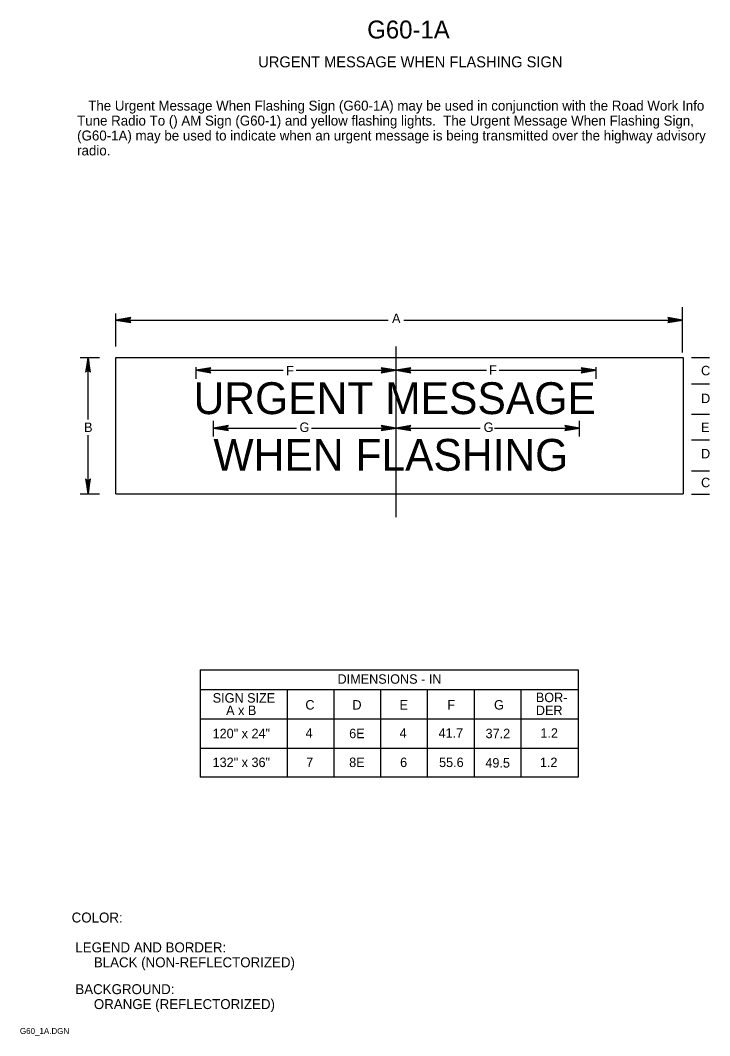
# Model space of a CAD drawing. Extents: x 0.012 to 0.185, y 0.004 to 0.259.
import ezdxf

# ---------------------------------------------------------------- set-up
doc = ezdxf.new("R2010")
doc.units = 0
doc.layers.add('1', color=7, linetype='Continuous')
doc.layers.add('3', color=7, linetype='Continuous')

# ---------------------------------------------------------------- blocks, each defined once
blk = doc.blocks.new('RARROW')
at = {"layer": '3'}
for p, q in [((-2.156, 0.285), (-2.2665, 0.384625)), ((-2.2665, 0.384625), (0, 0)), ((0, 0), (-2.2665, -0.379125)), ((-2.156, 0.285), (-2.075625, 0.12075)), ((0, 0), (-2.156, 0.285)), ((-2.14975, -0.2705), (0, 0)), ((-2.075625, 0.12075), (0, 0)), ((0, 0), (-2.074, -0.108)), ((-2.2665, -0.379125), (-2.14975, -0.2705)), ((-2.074, -0.108), (-2.14975, -0.2705))]:
    blk.add_line(p, q, dxfattribs=at)

msp = doc.modelspace()

# ---------------------------------------------------------------- linework, layer by layer
at = {"layer": '1'}
for p, q in [((0.17863, 0.17563), (0.17863, 0.187)), ((0.03625, 0.17713), (0.03625, 0.18538)), ((0.03625, 0.18375), (0.10462, 0.18375)), ((0.10862, 0.18375), (0.17863, 0.18375)), ((0.10662, 0.13425), (0.10662, 0.17713)), ((0.02725, 0.17438), (0.03213, 0.17438)), ((0.02925, 0.15875), (0.02925, 0.17438)), ((0.03625, 0.17438), (0.17875, 0.17438)), ((0.03625, 0.14012), (0.03625, 0.17438)), ((0.17875, 0.17438), (0.17875, 0.14012)), ((0.18088, 0.17438), (0.18538, 0.17438)), ((0.05638, 0.169), (0.05638, 0.17188)), ((0.05638, 0.17112), (0.07829, 0.17112)), ((0.0815, 0.17112), (0.10662, 0.17112)), ((0.10662, 0.16837), (0.10662, 0.17313)), ((0.10662, 0.17112), (0.12939, 0.17112)), ((0.1325, 0.17112), (0.15688, 0.17112)), ((0.15688, 0.169), (0.15688, 0.17188)), ((0.18088, 0.16775), (0.18538, 0.16775)), ((0.06074, 0.15453), (0.06074, 0.1584)), ((0.10662, 0.15453), (0.10662, 0.1584)), ((0.15275, 0.15453), (0.15275, 0.1584)), ((0.18088, 0.16012), (0.18538, 0.16012)), ((0.06086, 0.15663), (0.08163, 0.15663)), ((0.08535, 0.15663), (0.10662, 0.15663)), ((0.10662, 0.15663), (0.12775, 0.15663)), ((0.13139, 0.15663), (0.15275, 0.15663)), ((0.02925, 0.14012), (0.02925, 0.15481)), ((0.18088, 0.15363), (0.18538, 0.15363)), ((0.18088, 0.14588), (0.18538, 0.14588)), ((0.02725, 0.14012), (0.03213, 0.14012)), ((0.03625, 0.14012), (0.17875, 0.14012)), ((0.18088, 0.14), (0.18538, 0.14))]:
    msp.add_line(p, q, dxfattribs=at)
at = {"layer": '3'}
for p, q in [((0.05738, 0.09588), (0.15238, 0.09588)), ((0.05738, 0.09588), (0.05738, 0.06888)), ((0.15238, 0.09588), (0.15238, 0.06888)), ((0.15238, 0.09087), (0.05738, 0.09087)), ((0.07923, 0.0908), (0.07923, 0.06888)), ((0.09098, 0.0908), (0.09098, 0.06888)), ((0.10273, 0.0908), (0.10273, 0.06888)), ((0.10273, 0.0908), (0.10273, 0.07705)), ((0.11448, 0.0908), (0.11448, 0.06888)), ((0.12623, 0.0908), (0.12623, 0.06888)), ((0.13798, 0.0908), (0.13798, 0.06888)), ((0.15238, 0.0835), (0.05738, 0.0835)), ((0.15238, 0.07612), (0.05738, 0.07612)), ((0.15238, 0.06888), (0.05738, 0.06888))]:
    msp.add_line(p, q, dxfattribs=at)

# ---------------------------------------------------------------- block references
at = {"layer": '3', "xscale": 0.0016545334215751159, "yscale": -0.0016366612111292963}
for p, rotation in [((0.03625, 0.18375), 180), ((0.02925, 0.17438), 89.99999999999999), ((0.05638, 0.17112), 180), ((0.10662, 0.17112), 180), ((0.06075, 0.15663), 180), ((0.10662, 0.15663), 180), ((0.02925, 0.14012), -90.00000000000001)]:
    msp.add_blockref('RARROW', p, dxfattribs=dict(at, rotation=rotation))
for p in [(0.17863, 0.18375), (0.10662, 0.17112), (0.15688, 0.17112), (0.10662, 0.15663), (0.15275, 0.15663)]:
    msp.add_blockref('RARROW', p, dxfattribs=at)

# ---------------------------------------------------------------- texts
at = {"layer": '1'}
for s, height, p in [('G60-1A', 0.0045, (0.09938, 0.2545)), ('URGENT MESSAGE WHEN FLASHING SIGN', 0.0027503, (0.072, 0.24725)), ('   The Urgent Message When Flashing Sign (G60-1A) may be used in conjunction with the Road Work Info', 0.0024998, (0.0265, 0.23638)), ('Tune Radio To () AM Sign (G60-1) and yellow flashing lights.  The Urgent Message When Flashing Sign,', 0.0024998, (0.0265, 0.23262)), ('(G60-1A) may be used to indicate when an urgent message is being transmitted over the highway advisory', 0.00249975, (0.0265, 0.22887)), ('radio.', 0.0025, (0.0265, 0.22512)), ('A', 0.00238, (0.10562, 0.183)), ('F', 0.00238, (0.079, 0.16987)), ('F', 0.00238, (0.13, 0.17)), ('C', 0.00238, (0.18325, 0.16987)), ('URGENT MESSAGE', 0.0080003, (0.05575, 0.16012)), ('D', 0.00238, (0.18325, 0.16287)), ('B', 0.00238, (0.02825, 0.15563)), ('G', 0.00238, (0.08238, 0.15563)), ('G', 0.00238, (0.12862, 0.15563)), ('E', 0.00238, (0.18325, 0.15563)), ('WHEN FLASHING', 0.0080003, (0.06075, 0.14588)), ('D', 0.00238, (0.18325, 0.149)), ('C', 0.00238, (0.18325, 0.14175)), ('COLOR:', 0.0025, (0.02513, 0.03238)), (' LEGEND AND BORDER:', 0.0024998, (0.02513, 0.02488)), ('      BLACK (NON-REFLECTORIZED)', 0.0024998, (0.02513, 0.02113)), (' BACKGROUND:', 0.0024998, (0.02513, 0.01438)), ('      ORANGE (REFLECTORIZED)', 0.0024998, (0.02513, 0.01063)), ('G60_1A.DGN', 0.0015, (0.01213, 0.00438))]:
    msp.add_text(s, height=height, dxfattribs=at).set_placement(p)
at = {"layer": '3'}
for s, height, p in [('DIMENSIONS - IN', 0.0023752, (0.09192, 0.09237)), ('SIGN SIZE', 0.002375, (0.06056, 0.08763)), ('BOR-', 0.002375, (0.14175, 0.08775)), ('A x B', 0.002375, (0.06393, 0.0845)), ('C', 0.00238, (0.08385, 0.08588)), ('D', 0.00238, (0.09566, 0.08588)), ('E', 0.00238, (0.1075, 0.08588)), ('F', 0.00238, (0.1195, 0.08588)), ('G', 0.00238, (0.13125, 0.08588)), ('DER', 0.002375, (0.14175, 0.0845)), ('120" x 24"', 0.002375, (0.06053, 0.07869)), ('4', 0.00238, (0.08389, 0.07881)), ('6E', 0.002375, (0.09485, 0.07869)), ('4', 0.00238, (0.10751, 0.07881)), ('41.7', 0.002375, (0.11731, 0.07881)), ('37.2', 0.002375, (0.12911, 0.07869)), ('1.2', 0.002375, (0.14289, 0.07881)), ('132" x 36"', 0.002375, (0.06053, 0.07144)), ('7', 0.00238, (0.08406, 0.07144)), ('8E', 0.002375, (0.09485, 0.07144)), ('6', 0.00238, (0.10765, 0.07144)), ('55.6', 0.002375, (0.11743, 0.07144)), ('49.5', 0.002375, (0.12906, 0.07131)), ('1.2', 0.002375, (0.14276, 0.07144))]:
    msp.add_text(s, height=height, dxfattribs=at).set_placement(p)

doc.saveas('drawing.dxf')
